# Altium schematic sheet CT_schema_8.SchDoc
size 278 x 170 mm
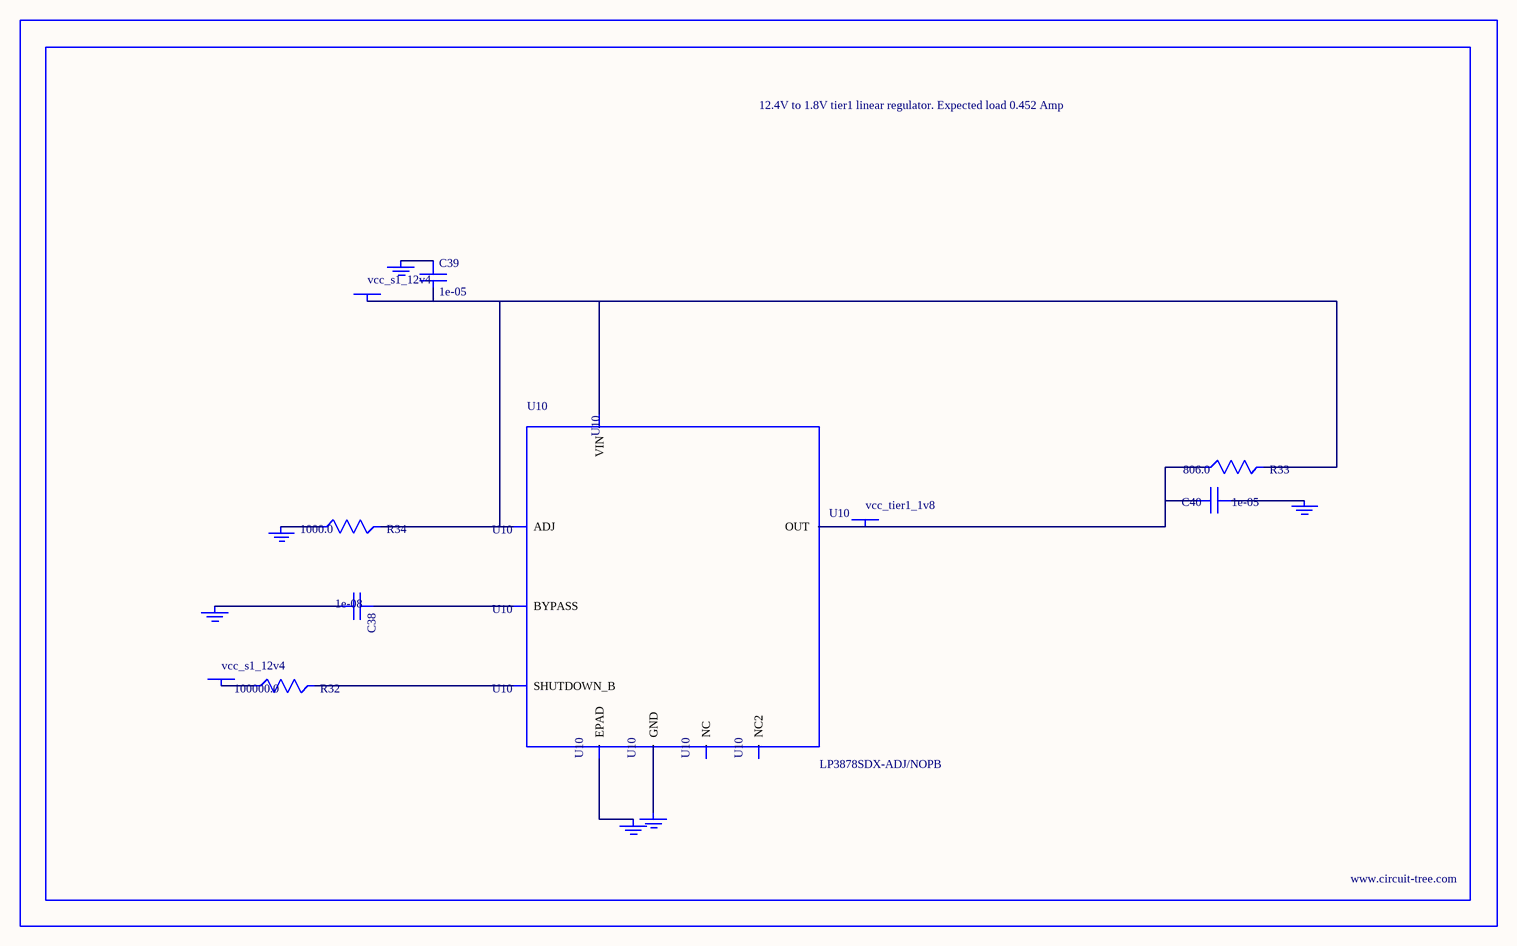
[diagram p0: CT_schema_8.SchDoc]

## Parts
BORDER7  (no value)
C38  1e-08  [C0402]
C39  1e-05  [C1210]
C40  1e-05  [C0805]
GND_INSTANCE_7_0  (no value)
GND_INSTANCE_7_1  (no value)
GND_INSTANCE_7_2  (no value)
GND_INSTANCE_7_3  (no value)
GND_INSTANCE_7_4  (no value)
GND_INSTANCE_7_5  (no value)
POWER_INSTANCE_7_0  vcc_s1_12v4
POWER_INSTANCE_7_1  vcc_s1_12v4
POWER_INSTANCE_7_2  vcc_tier1_1v8
R32  100000.0  [R0603]
R33  806.0  [R0603]
R34  1000.0  [R0603]
U10  LP3878SDX-ADJ/NOPB  [WSON-8]

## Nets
NetC38_1: C38.1 U10.1(BYPASS)
NetC38_2: C38.2 GND_INSTANCE_7_0.0(GND)
NetC39_1: C39.1 GND_INSTANCE_7_1.0(GND)
NetC39_2: C39.2 POWER_INSTANCE_7_0.0(PWR) R33.2 R34.2 U10.4(VIN) U10.6(ADJ)
NetC40_1: C40.1 GND_INSTANCE_7_2.0(GND)
NetC40_2: C40.2 POWER_INSTANCE_7_2.0(PWR) R33.1 U10.5(OUT)
NetGND_INSTANCE_7_3_0: GND_INSTANCE_7_3.0(GND) R34.1
NetGND_INSTANCE_7_4_0: GND_INSTANCE_7_4.0(GND) U10.PAD(EPAD)
NetGND_INSTANCE_7_5_0: GND_INSTANCE_7_5.0(GND) U10.3(GND)
NetPOWER_INSTANCE_7_1_0: POWER_INSTANCE_7_1.0(PWR) R32.1
NetR32_2: R32.2 U10.8(SHUTDOWN_B)

Not connected (* = marked no-connect by the designer): U10 2(NC) 7(NC2)

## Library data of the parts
BORDER7 = BORDER_PAGE7
C38 = C0402C103K3RAC
C39 = C1210C106K5PACTU
C40 = GRM219R60J106ME19D
GND_INSTANCE_7_0-GND_INSTANCE_7_5 = GND
POWER_INSTANCE_7_0-POWER_INSTANCE_7_2 = PWR
R32 = RC0603JR-07100KL
R33 = ERJ-3EKF8060V
R34 = RC0603JR-071KL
